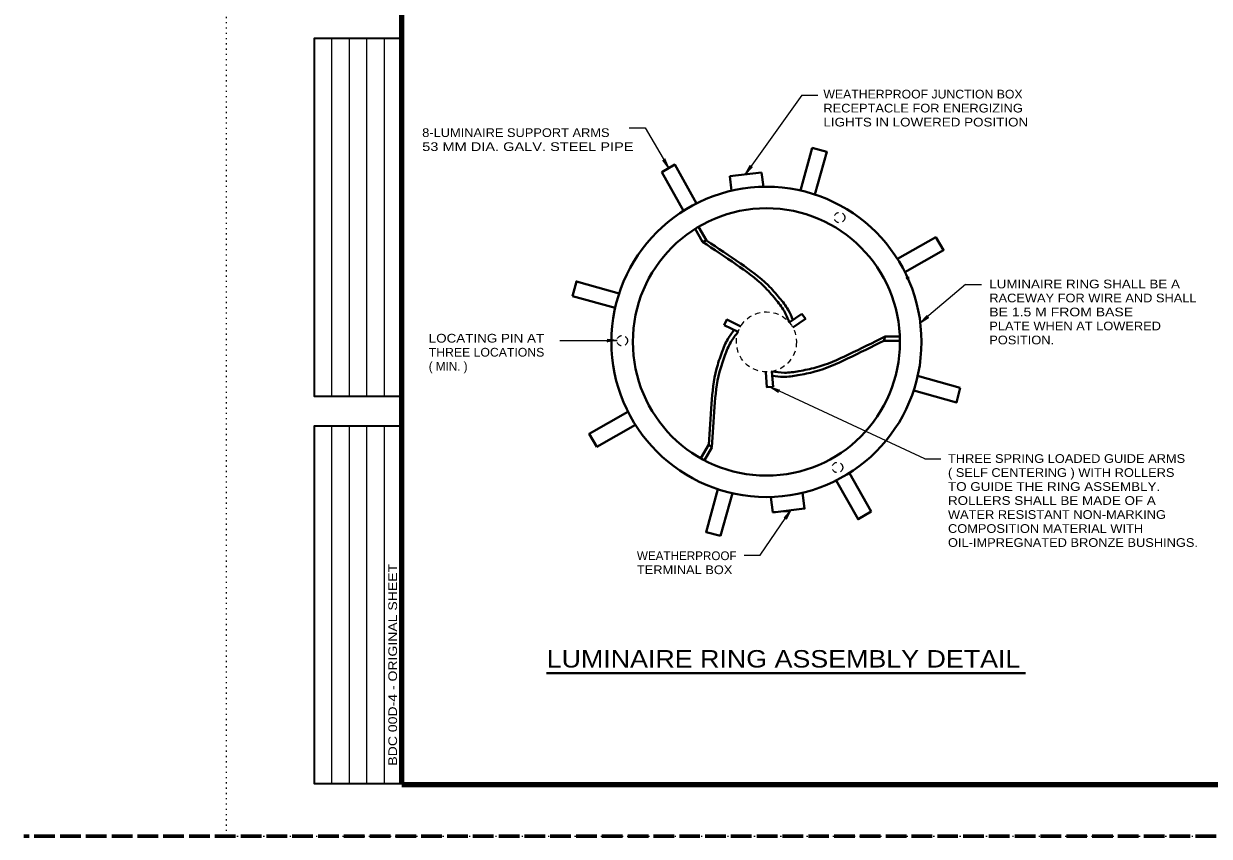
# Model space of a CAD drawing. Extents: x 312583 to 312854, y 144419 to 144597.
# Drawn here: x 312583.5 to 312686.9, y 144418.6 to 144489.4 of the extents above; entities that cross this region are included whole.
import ezdxf
from ezdxf.enums import TextEntityAlignment as Align

# ---------------------------------------------------------------- set-up
doc = ezdxf.new("R2010")
doc.units = 0
doc.header["$LTSCALE"] = 0.3
doc.header["$PDMODE"] = 32
doc.header["$PDSIZE"] = 0.15
for name, pattern in [('DOTTED', [1.5, 0.3, -1.2]), ('LONG_DASHED', [7.5, 6, -1.5]), ('SHORT_DASHED', [2.7, 1.5, -1.2])]:
    doc.linetypes.add(name, pattern=pattern)
for name, color, linetype, lineweight in [('1', 7, 'Continuous', 40), ('2', 7, 'Continuous', 13), ('62', 7, 'DOTTED', 13), ('63', 7, 'LONG_DASHED', 60)]:
    doc.layers.add(name, color=color, linetype=linetype, lineweight=lineweight)

msp = doc.modelspace()

# ---------------------------------------------------------------- linework, layer by layer
at = {"layer": '1', "lineweight": 25}
for p, q in [((312610.4087, 144456.901), (312610.4087, 144488.1192)), ((312611.9315, 144456.901), (312611.9315, 144488.1192)), ((312613.4543, 144456.901), (312613.4543, 144488.1192)), ((312614.9772, 144456.901), (312614.9772, 144488.1192)), ((312610.4087, 144423.1446), (312610.4087, 144454.3629)), ((312611.9315, 144423.1446), (312611.9315, 144454.3629)), ((312613.4543, 144423.1446), (312613.4543, 144454.3629)), ((312614.9772, 144423.1446), (312614.9772, 144454.3629))]:
    msp.add_line(p, q, dxfattribs=at)
at = {"layer": '1'}
for p, q in [((312652.2895, 144478.5746), (312651.2622, 144474.8486)), ((312639.1642, 144476.4433), (312641.0655, 144473.0853)), ((312645.0982, 144476.0906), (312647.8735, 144476.4356)), ((312648.0345, 144475.1783), (312647.8735, 144476.4356)), ((312645.2592, 144474.8333), (312645.0982, 144476.0906)), ((312642.0699, 144471.506), (312642.7215, 144470.3866)), ((312642.3765, 144471.69), (312643.0742, 144470.4863)), ((312643.0742, 144470.4863), (312642.7292, 144470.3866)), ((312663.0765, 144470.793), (312659.7185, 144468.8916)), ((312631.3902, 144465.6563), (312635.1085, 144464.629)), ((312651.3925, 144464.1153), (312650.2885, 144463.364)), ((312644.6229, 144463.1186), (312645.8265, 144462.536)), ((312658.5455, 144461.7693), (312658.6375, 144462.122)), ((312659.9409, 144461.7693), (312658.5455, 144461.7693)), ((312659.9332, 144462.1296), (312658.6375, 144462.1296)), ((312648.8702, 144457.752), (312648.7705, 144459.086)), ((312665.2002, 144457.6676), (312661.4819, 144458.695)), ((312633.5139, 144452.531), (312636.8719, 144454.4323)), ((312642.5682, 144451.519), (312643.2659, 144452.7303)), ((312642.8825, 144451.3503), (312643.5265, 144452.4696)), ((312643.2659, 144452.7303), (312643.5189, 144452.4773)), ((312657.4262, 144446.8806), (312655.5249, 144450.2386)), ((312644.3009, 144444.757), (312645.3282, 144448.4753)), ((312648.8472, 144446.7963), (312648.6709, 144448.1456))]:
    msp.add_line(p, q, dxfattribs=at)
at = {"layer": '1', "lineweight": 158}
msp.add_line((312616.5, 144423.0846), (312849, 144423.0846), dxfattribs=at)
msp.add_lwpolyline([(312616.5, 144423.1446), (312616.5, 144585.0846), (312849, 144585.0846)], dxfattribs=at)
at = {"layer": '1', "lineweight": 35}
for points in [[(312616.5, 144456.901), (312608.8858, 144456.901), (312608.8858, 144488.1192), (312616.5, 144488.1192)], [(312616.5, 144423.1446), (312608.8858, 144423.1446), (312608.8858, 144454.3629), (312616.5, 144454.3629)]]:
    msp.add_lwpolyline(points, dxfattribs=at)
at = {"layer": '1'}
for points in [[(312652.2895, 144478.5746), (312653.5622, 144478.2373), (312652.5272, 144474.5036)], [(312639.1642, 144476.4433), (312640.2989, 144477.1103), (312642.2079, 144473.737)], [(312663.0765, 144470.793), (312663.7435, 144469.6583), (312660.3702, 144467.7493)], [(312631.3902, 144465.6563), (312631.7199, 144466.929), (312635.4535, 144465.894)], [(312650.5952, 144462.927), (312651.6992, 144463.6706), (312651.3925, 144464.1153)], [(312646.0489, 144463.019), (312644.8529, 144463.6093), (312644.6229, 144463.1186)], [(312648.2415, 144459.04), (312648.3335, 144457.7136), (312648.8702, 144457.752)], [(312665.2002, 144457.6676), (312664.8705, 144456.395), (312661.1369, 144457.43)], [(312633.5139, 144452.531), (312632.8469, 144453.6656), (312636.2202, 144455.5746)], [(312657.4262, 144446.8806), (312656.2915, 144446.2136), (312654.3825, 144449.587)], [(312644.3009, 144444.757), (312643.0282, 144445.0866), (312644.0632, 144448.8203)], [(312648.8472, 144446.7963), (312651.6225, 144447.1413), (312651.4462, 144448.5136)]]:
    msp.add_lwpolyline(points, dxfattribs=at)
for radius in [13.5189, 11.6474]:
    msp.add_circle((312648.2952, 144461.662), radius, dxfattribs=at)
at = {"layer": '1', "linetype": 'SHORT_DASHED', "lineweight": 25}
for centre, radius in [((312654.6725, 144472.4969), 0.4565), ((312648.2952, 144461.662), 2.6195), ((312635.7233, 144461.7674), 0.4565), ((312654.4899, 144450.7216), 0.4565)]:
    msp.add_circle(centre, radius, dxfattribs=at)
at = {"layer": '1'}
for points in [[(312642.7215, 144470.3866), (312645.6655, 144468.4086), (312648.0729, 144466.5073), (312649.0849, 144465.388), (312649.8362, 144464.3606), (312650.2885, 144463.364)], [(312643.0742, 144470.4863), (312646.0259, 144468.5083), (312648.4332, 144466.607), (312649.4452, 144465.4876), (312650.1965, 144464.4603), (312650.5952, 144463.5786)], [(312643.2659, 144452.7303), (312643.5035, 144456.2723), (312643.9405, 144459.3083), (312644.4082, 144460.742), (312644.9219, 144461.9073), (312645.4815, 144462.697)], [(312643.5265, 144452.4696), (312643.7642, 144456.0116), (312644.2089, 144459.0476), (312644.6765, 144460.4813), (312645.1902, 144461.6466), (312645.8265, 144462.536)], [(312658.6375, 144462.1296), (312655.4559, 144460.5656), (312652.6039, 144459.431), (312651.1242, 144459.1166), (312649.8592, 144458.9786), (312648.7705, 144459.086)], [(312658.5455, 144461.7693), (312655.3639, 144460.2053), (312652.5119, 144459.0706), (312651.0322, 144458.7563), (312649.7672, 144458.6183), (312648.8012, 144458.7103)]]:
    msp.add_spline(points, degree=3, dxfattribs=at)
msp.add_point((312660.6079, 144467.2433), dxfattribs=at)
at = {"layer": '2'}
for p, q in [((312651.3849, 144483.167), (312646.4552, 144476.2593)), ((312651.3849, 144483.167), (312652.7802, 144483.167)), ((312639.2562, 144477.5013), (312639.4862, 144477.3173)), ((312639.7852, 144476.8113), (312639.2562, 144477.5013)), ((312639.4402, 144477.6086), (312639.4862, 144477.3173)), ((312639.7852, 144476.8113), (312639.4402, 144477.6086)), ((312646.4552, 144476.2593), (312646.8692, 144477.026)), ((312646.4552, 144476.2593), (312647.0455, 144476.9033)), ((312646.8692, 144477.026), (312646.8002, 144476.7423)), ((312647.0455, 144476.9033), (312646.8002, 144476.7423)), ((312665.6525, 144466.6683), (312661.7119, 144463.318)), ((312665.6525, 144466.6683), (312667.0479, 144466.6683)), ((312661.7119, 144463.318), (312662.3022, 144463.962)), ((312661.7119, 144463.318), (312662.4402, 144463.801)), ((312662.3022, 144463.962), (312662.1642, 144463.7013)), ((312662.4402, 144463.801), (312662.1642, 144463.7013)), ((312630.2785, 144461.777), (312635.2695, 144461.777)), ((312634.4032, 144461.8843), (312634.6792, 144461.777)), ((312635.2695, 144461.777), (312634.4032, 144461.8843)), ((312634.4032, 144461.6696), (312634.6792, 144461.777)), ((312635.2695, 144461.777), (312634.4032, 144461.6696)), ((312662.1182, 144451.473), (312648.6095, 144457.7366)), ((312648.6095, 144457.7366), (312649.3532, 144457.2766)), ((312648.6095, 144457.7366), (312649.4375, 144457.4683)), ((312649.3532, 144457.2766), (312649.1462, 144457.4913)), ((312649.4375, 144457.4683), (312649.1462, 144457.4913)), ((312662.1182, 144451.473), (312663.5135, 144451.473)), ((312647.7585, 144443.078), (312650.4189, 144446.988)), ((312648.9392, 144446.896), (312650.3345, 144446.896)), ((312650.4189, 144446.988), (312649.8439, 144446.3286)), ((312649.8439, 144446.3286), (312650.0892, 144446.4973)), ((312650.4189, 144446.988), (312650.0202, 144446.2136)), ((312650.0202, 144446.2136), (312650.0892, 144446.4973)), ((312646.3632, 144443.078), (312647.7585, 144443.078))]:
    msp.add_line(p, q, dxfattribs=at)
at = {"layer": '2', "lineweight": 40}
msp.add_line((312629.1206, 144432.793), (312670.878, 144432.793), dxfattribs=at)
at = {"layer": '2'}
msp.add_lwpolyline([(312636.3352, 144480.3073), (312637.7305, 144480.3073), (312639.7852, 144476.8113)], dxfattribs=at)
at = {"layer": '62'}
msp.add_line((312601.2, 144418.5846), (312601.2, 144596.7846), dxfattribs=at)
msp.add_lwpolyline([(312601.2, 144418.5846), (312853.5, 144418.5846), (312853.5, 144596.7846)], dxfattribs=at)
at = {"layer": '63'}
msp.add_line((312851.75, 144418.5846), (312583.526, 144418.5846), dxfattribs=at)

# ---------------------------------------------------------------- texts
at = {"layer": '1', "width": 1.2}
msp.add_text('BDC 00D-4 - ORIGINAL SHEET', height=0.7614, rotation=90, dxfattribs=at).set_placement((312616.0832, 144424.7374))
at = {"layer": '2'}
for s, width, p in [('WEATHERPROOF JUNCTION BOX', 1.05, (312653.2632, 144482.8746)), ('RECEPTACLE FOR ENERGIZING', 1.1, (312653.2632, 144481.6546)), ('LIGHTS IN LOWERED POSITION', 1.15, (312653.2632, 144480.4346)), ('8-LUMINAIRE SUPPORT ARMS', 1.1, (312618.2771, 144479.5173)), ('53 MM DIA. GALV. STEEL PIPE', 1.25, (312618.2771, 144478.2973)), ('LUMINAIRE RING SHALL BE A', 1.15, (312667.7302, 144466.33)), ('RACEWAY FOR WIRE AND SHALL', 1.1, (312667.7302, 144465.11)), ('BE 1.5 M FROM BASE', 1.2, (312667.7302, 144463.89)), ('PLATE WHEN AT LOWERED', 1.1, (312667.7302, 144462.67)), ('LOCATING PIN AT', 1.15, (312618.845, 144461.6019)), ('POSITION.', 1.1, (312667.7302, 144461.45)), ('THREE LOCATIONS', 1.05, (312618.845, 144460.3819)), ('THREE SPRING LOADED GUIDE ARMS', 1.1, (312664.1269, 144451.1193)), ('( SELF CENTERING ) WITH ROLLERS', 1.1, (312664.1269, 144449.8993)), ('TO GUIDE THE RING ASSEMBLY.', 1.15, (312664.1269, 144448.6793)), ('ROLLERS SHALL BE MADE OF A', 1.15, (312664.1269, 144447.4593)), ('WATER RESISTANT NON-MARKING', 1.1, (312664.1269, 144446.2393)), ('COMPOSITION MATERIAL WITH', 1.1, (312664.1269, 144445.0193)), ('OIL-IMPREGNATED BRONZE BUSHINGS.', 1.1, (312664.1269, 144443.7993)), ('TERMINAL BOX', 1.1, (312637.0005, 144441.4276))]:
    msp.add_text(s, height=0.76, dxfattribs=dict(at, width=width)).set_placement(p)
for s, p in [('( MIN. )', (312618.845, 144459.1619)), ('WEATHERPROOF', (312637.0005, 144442.6476))]:
    msp.add_text(s, height=0.76, dxfattribs=at).set_placement(p)
at = {"layer": '2', "width": 1.15}
msp.add_text('LUMINAIRE RING ASSEMBLY DETAIL', height=1.52, dxfattribs=at).set_placement((312649.7854, 144433.2883), align=Align.CENTER)

doc.saveas('drawing.dxf')
